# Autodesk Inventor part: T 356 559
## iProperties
Company: Mayer & Müller AG Schaltgeräte
Created: 2005-12
Part Number: T 356 559
Material: Polyamid
Document SubType Name: Modeling
Designer: I.Baliuc
Manufacturer: Standard
Standards Organization: Custom
Description: Bolzen
Density: 1.42 g/cm^3
Abmessung: Rd 12
Author: T.Messerschmitt
Keywords: 213542
Revision Number: 356559
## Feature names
1. Extrusion2
2. Fase1 [Chamfer]
